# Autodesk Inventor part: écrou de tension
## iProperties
Shininess: 64.0
Length Units: 11269
Angle Units: 11279
Time Units: 11290
Mass Units: 11283
Length Display Precision: 3
Angle Display Precision: 2
Compacted: True
Part Number: écrou de tension
Document SubType Name: Modeling
Created: 2004-12
Material: Par défaut
Designer: LEGERET Philippe
Density: 0.0
Volumn: 0.0
Area: 0.0
PropertySet Name: Model Information
Control State: 0
Master: False
Checked Out: False
Author: LEGERET Philippe
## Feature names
1. Extrusion1
2. Perçage1 [Hole]
3. Perçage2 [Hole]
4. Extrusion2
